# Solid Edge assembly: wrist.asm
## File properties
Author: nakano
Template: iso metric assembly.asm
Last saved by: nakano
Revision: 2
Application: Solid Edge
Username: nakano
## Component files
ASB-26Ver3.par
Hitec HS-225 MG.par
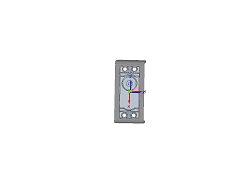
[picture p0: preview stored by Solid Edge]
